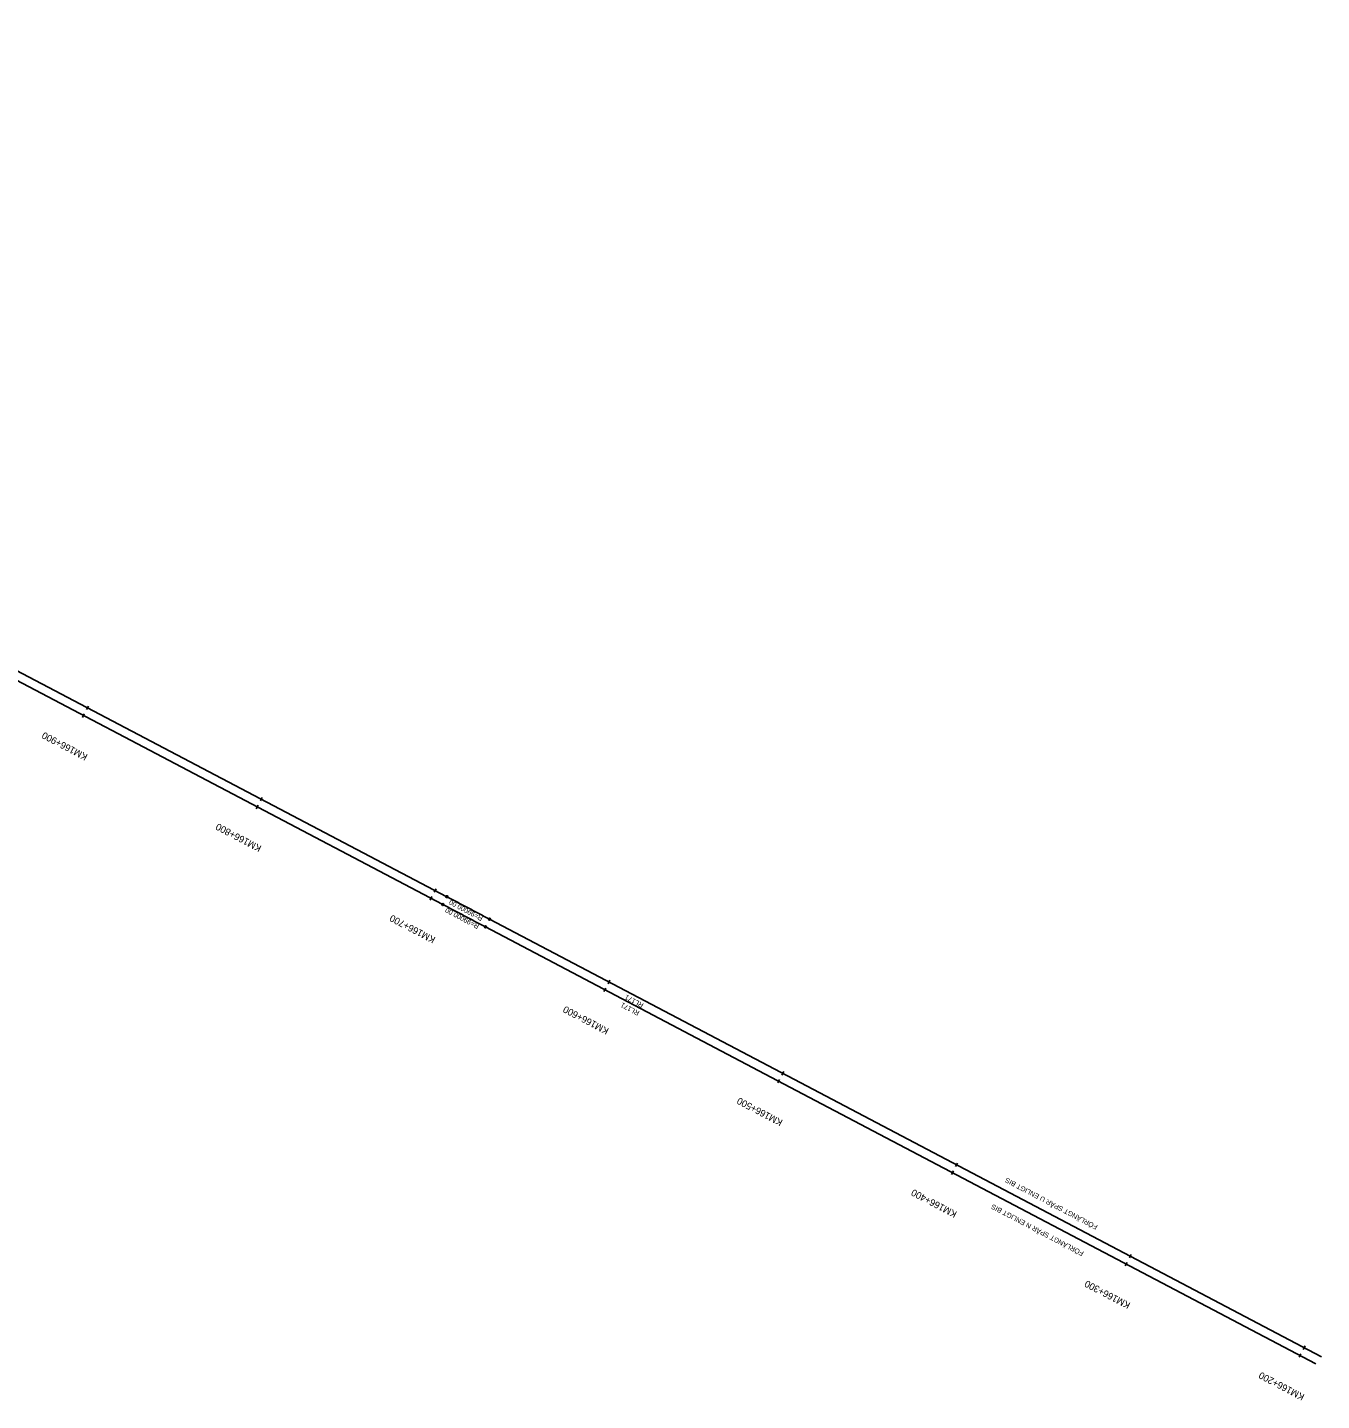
# Model space of a CAD drawing. Extents: x 185262 to 188870, y 6548921 to 6550022.
# Drawn here: x 188211 to 188870, y 6548921 to 6549621 of the extents above; entities that cross this region are included whole.
import ezdxf

# ---------------------------------------------------------------- set-up
doc = ezdxf.new("R2010")
doc.units = 0
for name, color, linetype in [('Befintlig spårmitt enligt BIS', 7, 'Continuous'), ('Längdm markering (primär) L', 7, 'Continuous'), ('Längdmätning T', 7, 'Continuous'), ('Spår bef projekterat behålls L', 7, 'Continuous'), ('Spår nr T', 7, 'Continuous'), ('Spårgeometri T', 7, 'Continuous'), ('Spårmitt tp P', 7, 'Continuous')]:
    doc.layers.add(name, color=color, linetype=linetype)

msp = doc.modelspace()

# ---------------------------------------------------------------- linework, layer by layer
at = {"layer": 'Befintlig spårmitt enligt BIS'}
for p, q in [((188870.23, 6548943.7), (188598.34, 6549086.73)), ((188867.25, 6548940.19), (188596.25, 6549082.75))]:
    msp.add_line(p, q, dxfattribs=at)
at = {"layer": 'Längdm markering (primär) L'}
for points in [[(188241.38, 6549273.32), (188242.31, 6549275.09)], [(188239.28, 6549269.33), (188240.22, 6549271.1)], [(188329.89, 6549226.78), (188330.82, 6549228.55)], [(188327.8, 6549222.8), (188328.73, 6549224.57)], [(188416.31, 6549176.27), (188417.24, 6549178.04)], [(188418.41, 6549180.25), (188419.34, 6549182.02)], [(188506.91, 6549133.7), (188507.84, 6549135.47)], [(188504.82, 6549129.71), (188505.75, 6549131.48)], [(188595.41, 6549087.14), (188596.34, 6549088.91)], [(188593.32, 6549083.16), (188594.25, 6549084.93)], [(188681.82, 6549036.6), (188682.75, 6549038.37)], [(188683.91, 6549040.59), (188684.84, 6549042.36)], [(188772.41, 6548994.03), (188773.35, 6548995.8)], [(188770.32, 6548990.05), (188771.25, 6548991.82)], [(188860.92, 6548947.48), (188861.85, 6548949.25)], [(188858.82, 6548943.49), (188859.75, 6548945.26)]]:
    msp.add_lwpolyline(points, dxfattribs=at)
at = {"layer": 'Spår bef projekterat behålls L'}
for p, q in [((188422.73, 6549174.02), (187573.24, 6549620.62)), ((188424.82, 6549178.01), (187719.61, 6549548.75)), ((188598.34, 6549086.73), (188446.56, 6549166.57)), ((188596.25, 6549082.75), (188444.47, 6549162.59))]:
    msp.add_line(p, q, dxfattribs=at)
for centre in [(142356.53, 6461549.74), (142354.44, 6461545.76)]:
    msp.add_arc(centre, 99000, 62.253797, 62.2680151, dxfattribs=at)
at = {"layer": 'Spårmitt tp P'}
for centre in [(188424.82, 6549178.01), (188422.73, 6549174.02), (188444.47, 6549162.59), (188446.56, 6549166.57)]:
    msp.add_circle(centre, 0.5, dxfattribs=at)

# ---------------------------------------------------------------- texts
at = {"layer": 'Längdmätning T'}
for s, rotation, p in [('KM166+900', 152.26802, (188242.24, 6549250.27)), ('KM166+800', 152.26802, (188330.77, 6549203.73)), ('KM166+700', 152.26802, (188419.32, 6549157.17)), ('KM166+600', 152.2538, (188507.64, 6549110.72)), ('KM166+500', 152.2538, (188596.17, 6549064.14)), ('KM166+400', 152.2538, (188684.91, 6549017.46)), ('KM166+300', 152.2538, (188773.19, 6548971.02)), ('KM166+200', 152.2538, (188861.89, 6548924.37))]:
    msp.add_text(s, height=3.5, rotation=rotation, dxfattribs=at).set_placement(p)
at = {"layer": 'Spår nr T'}
for s, p in [('FÖRLÄNGT SPÅR U ENLIGT BIS', (188756.48, 6549010.56)), ('FÖRLÄNGT SPÅR N ENLIGT BIS', (188749.4, 6548997.09))]:
    msp.add_text(s, height=2.5, rotation=152.26802, dxfattribs=at).set_placement(p)
at = {"layer": 'Spårgeometri T'}
for s, rotation, p in [('R=99000.00', 152.00779, (188441.52, 6549163.66)), ('R=99000.00', 152.00779, (188443.45, 6549167.72)), ('RL171', 152.2538, (188523.16, 6549119.51)), ('RL171', 152.2538, (188525.25, 6549123.5))]:
    msp.add_text(s, height=2.5, rotation=rotation, dxfattribs=at).set_placement(p)

doc.saveas('drawing.dxf')
